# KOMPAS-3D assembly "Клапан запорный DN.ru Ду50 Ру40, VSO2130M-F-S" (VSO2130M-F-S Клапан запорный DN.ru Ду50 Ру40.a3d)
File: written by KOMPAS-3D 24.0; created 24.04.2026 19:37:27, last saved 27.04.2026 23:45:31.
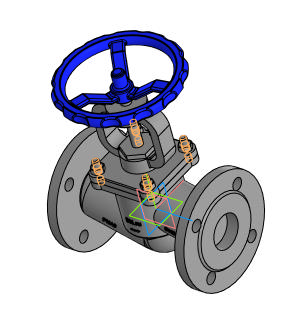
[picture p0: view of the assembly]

Document properties: Автор: DN.ru; Полное имя файла: C:\Работа\ГОТОВЫЕ ИСХОДНИКИ\VSO2130M-F-S Клапан запорный сальниковый DN.ru Ду15-100 Ру40\исходные материалы\DN50\VSO2130M-F-S Клапан запорный DN.ru Ду50 Ру40.a3d

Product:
- Component [detail]: Корпус  | qty 1  | pos. 1  | Масса: 6.9; Автор: R2D2; source file: Korpus.m3d
- Component [detail]: Деталь  | qty 1  | pos. 2  | Масса: 2.243083; Автор: mrdid; source file: rama.m3d
- Component [detail]: Деталь2  | qty 1  | pos. 3  | Масса: 1.255283; Автор: R2D2; additional columns: Типовые; source file: shturval.m3d
- Component [standard]: Шпилька М10-6gx30 ГОСТ 22032-76  | qty 4  | Масса: 0.021; Раздел спецификации: Стандартные изделия; Рассекать на разрезах: no
- Component [standard]: Гайка М10-6H ГОСТ 5915-70  | qty 4  | Масса: 0.01206; Раздел спецификации: Стандартные изделия; Рассекать на разрезах: no
- Part/product: Клапан запорный DN.ru Ду50 Ру40  | designation VSO2130M-F-S
    Масса: 15
    Раздел спецификации: Прочие изделия
    Примечание: D090-01984

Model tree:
1. Контекстная связь:1  (with: Контекстная связь (Деталь):1)  (labels: Грань.Твердое тело1)
2. Контекстная связь:2  (with: Смещенная плоскость:4, Контекстная связь (Деталь):2)  (labels: Грань.Твердое тело1)
3. Контекстная связь:3  (with: Контекстная связь (Корпус):3)
4. Контекстная связь:4  (with: Эскиз:2, Ребро.Элемент выдавливания:14, Контекстная связь (Деталь):4)
5. Контекстная связь:5  (with: Контекстная связь (Деталь):5)
6. Массив по концентрической сетке:1  (with: Грань.Элемент выдавливания:1, Грань.Элемент выдавливания:15, Грань.Элемент выдавливания:3, Грань.Элемент выдавливания:2, Грань.Элемент выдавливания:16, Грань.Элемент выдавливания:14)  (labels: Грань.Твердое тело1; Грань.Элемент выдавливания:16.Экземпляр ( 1, 4 ))  (4 pattern instances)
     Шаг 2 = 360; Угол = 9

Referenced files in C:\Работа\ГОТОВЫЕ ИСХОДНИКИ\VSO2130M-F-S Клапан запорный сальниковый DN.ru Ду15-100 Ру40\исходные материалы\DN50\: Korpus.m3d, rama.m3d, shturval.m3d
Referenced files in C:\Program Files\ASCON\KOMPAS-3D v24\Libs\PolynomLib\DATA\vault\Methods\Kompas\3D\: PLib_Stud_1_900.m3d, PLib_Nut_OST92_900.m3d
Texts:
  Крепежное изделие ГОСТ
  BOSimple***PART:d53d3cf6-5b70-9c3a-e6c8-4c3190dd645a***SHORTLOC:Root±30±20±10±120±10±20[Нет;Без покрытия;Без указания материала;-;10;30;1,5;1,5]
  BOSimple***PART:2c395b93-8c4a-cf39-bcf6-f45056cee6ca***SHORTLOC:Root±30±10±20±©{}110±10±50±60[Нет;Без покрытия;Без указания материала;-;10;1,5;17]
  Программные изделия  и базы данных
  VSO2130M-F-S
  Деталь2 Деталь2
  Шпилька М10-6gx30 ГОСТ 22032-76 (1)
  cut1
  Гайка М10-6H ГОСТ 5915-70 (1)
  bcut1
  hole1
  hcut1
  hole2
  Шпилька М10-6gx30 ГОСТ 22032-76 (2)
  Гайка М10-6H ГОСТ 5915-70 (2)
  Шпилька М10-6gx30 ГОСТ 22032-76 (3)
  Гайка М10-6H ГОСТ 5915-70 (3)
  Шпилька М10-6gx30 ГОСТ 22032-76 (4)
  Гайка М10-6H ГОСТ 5915-70 (4)
  Плоскость ZX.Начало координат
  Плоскость XY.Начало координат
  Plane. Начало координат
